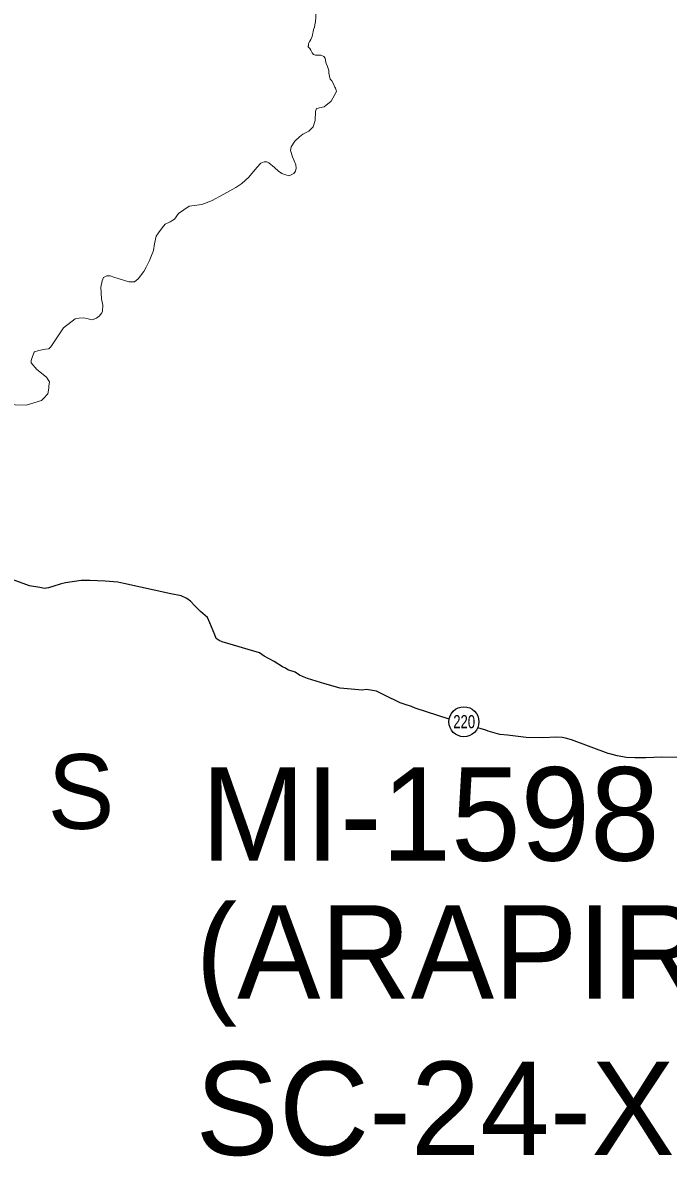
# Model space of a CAD drawing. Extents: x 553962 to 842807, y 8883888 to 9032388.
# Drawn here: x 609594 to 613049, y 8902991 to 8909058 of the extents above; entities that cross this region are included whole.
import ezdxf
from ezdxf.enums import TextEntityAlignment as Align

# ---------------------------------------------------------------- set-up
doc = ezdxf.new("R2010")
doc.units = 0
doc.header["$LTSCALE"] = 200
doc.layers.add('6', color=7, linetype='Continuous', lineweight=13)

msp = doc.modelspace()

# ---------------------------------------------------------------- linework, layer by layer
at = {"layer": '6', "lineweight": 25}
msp.add_line((612071.6, 8905270.5), (612029.8, 8905283.1), dxfattribs=at)
at = {"layer": '6'}
for points in [[(611132.8, 8909169.8), (611140.8, 8909154.6), (611149.8, 8909140.2), (611156.9, 8909130), (611161.9, 8909111.7), (611162.8, 8909101.5), (611162.7, 8909086.2), (611161.5, 8909063.8), (611158.3, 8909046.5), (611155.2, 8909034.3), (611151.1, 8909021.1), (611147.9, 8909008.9), (611144.8, 8908994.6), (611143.7, 8908983.4), (611136.5, 8908968.2), (611130.3, 8908959.1), (611124.1, 8908945.9), (611123, 8908934.7), (611120.9, 8908932.7)], [(611120.8, 8908930.9), (611124, 8908927.7), (611130, 8908919.5), (611136.1, 8908910.3), (611144.1, 8908897), (611151.2, 8908887.8), (611160.3, 8908883.7), (611173.5, 8908884.6), (611188.8, 8908884.5), (611205, 8908876.3), (611213.1, 8908867.1), (611214, 8908854.8), (611219, 8908838.5), (611225, 8908824.2), (611233, 8908802.8), (611232.9, 8908788.5), (611235.8, 8908772.2), (611239.8, 8908754.9), (611248.8, 8908746.7), (611254.9, 8908733.4), (611264.8, 8908712.2), (611264.8, 8908712.1)], [(611264.8, 8908712.2), (611267.8, 8908707.6), (611272.5, 8908697.4), (611273.2, 8908690.4), (611244.6, 8908638.1), (611206.9, 8908607.9), (611166.1, 8908597.7), (611161.7, 8908583.1), (611160.2, 8908534.8), (611148.5, 8908499.8), (611125.2, 8908476.4), (611093.1, 8908461.8), (611075.5, 8908447.2), (611050.7, 8908423.8), (611031.8, 8908393.1), (611027.4, 8908374.1), (611037.6, 8908339), (611055.1, 8908296.7), (611058, 8908279.1), (611053.7, 8908263.1), (611044.9, 8908249.9), (611020.1, 8908238.2), (611002.6, 8908244.1), (610980.7, 8908251.4), (610963.1, 8908263.1), (610941.2, 8908282), (610910.6, 8908306.9), (610900.4, 8908312.7), (610885.8, 8908312.7), (610868.3, 8908305.4), (610847.8, 8908283.5), (610804, 8908230.9), (610767.5, 8908197.3), (610734, 8908175.4), (610671.2, 8908140.3), (610605.5, 8908105.2), (610553, 8908084.8)], [(610553, 8908084.8), (610485.8, 8908076), (610427.4, 8908036.6), (610407, 8908005.9), (610383.6, 8907991.2), (610357.4, 8907979.6), (610341.3, 8907960.6), (610320.9, 8907932.8), (610309.2, 8907915.3), (610299, 8907874.3), (610294.6, 8907839.3), (610272.7, 8907785.2), (610255.2, 8907748.7), (610242, 8907725.3), (610212.8, 8907687.3), (610192.4, 8907671.2), (610163.2, 8907671.2), (610134, 8907680), (610081.5, 8907696.1), (610062.5, 8907703.4), (610045, 8907703.4), (610027.5, 8907694.6), (610020.2, 8907675.6), (610012.9, 8907642), (610015.8, 8907579.2), (610023.1, 8907545.6), (610021.6, 8907513.4), (610017.2, 8907504.6), (610004.1, 8907487.1), (609989.5, 8907476.9), (609966.2, 8907468.1), (609938.4, 8907473.9), (609920.9, 8907478.3), (609894.6, 8907476.9), (609875.6, 8907472.5), (609812.9, 8907424.3), (609763.2, 8907349.7), (609745.7, 8907323.4), (609734.1, 8907311.8), (609716.5, 8907310.3), (609681.5, 8907303), (609658.1, 8907297.1), (609655.2, 8907294.2), (609646.5, 8907270.8), (609640.6, 8907250.4), (609640.6, 8907237.2), (609669.8, 8907202.2), (609722.4, 8907159.8), (609731.1, 8907146.6), (609738.4, 8907134.9), (609734.1, 8907113), (609734.1, 8907101.3), (609728.2, 8907072.1), (609706.3, 8907047.2), (609694.6, 8907035.6), (609612.9, 8907010.7), (609494.7, 8907013.6)]]:
    msp.add_lwpolyline(points, dxfattribs=at)
at = {"layer": '6', "lineweight": 25}
for points in [[(609711.8, 8906029), (609686.4, 8906034.2), (609630.4, 8906044.4), (609398.4, 8906127.4)], [(611876.2, 8905330.5), (611694.3, 8905389.6), (611673.9, 8905398.8), (611640.3, 8905409.1), (611614.9, 8905418.3), (611529.5, 8905459.2), (611487.8, 8905480.7), (611434.8, 8905488.9), (611411.4, 8905485.9), (611293.2, 8905495.3), (611210.8, 8905518.9), (611119.2, 8905548.6), (611091.7, 8905557.8), (611075.4, 8905566), (611053.1, 8905581.3), (611012.4, 8905594.7), (611001.2, 8905603.8), (610983.9, 8905611), (610939.2, 8905638.6), (610887.3, 8905668.2), (610861.9, 8905685.6), (610662.4, 8905744), (610646.2, 8905751.2), (610629.9, 8905762.4), (610621.8, 8905781.8), (610596.6, 8905846), (610582.4, 8905873.6), (610545.9, 8905906.2), (610516.4, 8905936.9), (610492.1, 8905961.4), (610472.8, 8905975.7), (610442.2, 8905990), (610387.3, 8906001.3), (610135.8, 8906056.8), (610104.2, 8906062.9), (610036, 8906069.2), (609954.5, 8906072.4), (609907.6, 8906072.5), (609824.1, 8906060.4), (609794.5, 8906053.3), (609760.8, 8906041.2), (609733.3, 8906033.1), (609711.8, 8906029)], [(612735.8, 8905143.9), (612726.5, 8905147.3), (612530.1, 8905219), (612498.6, 8905228.2), (612481.3, 8905232.3), (612452.7, 8905234.4), (612376.3, 8905230.5), (612288.7, 8905232.7), (612187.9, 8905244.1), (612147.1, 8905248.2), (612085.1, 8905265.6), (612071.6, 8905270.5)], [(613111.5, 8905124.2), (613014.8, 8905127.4), (612929.2, 8905123.5), (612870.1, 8905123.6), (612825.2, 8905124.7), (612775.3, 8905133.9), (612735.8, 8905143.9)]]:
    msp.add_lwpolyline(points, dxfattribs=at)
msp.add_circle((611955.2, 8905316.5), 80.3, dxfattribs=at)

# ---------------------------------------------------------------- texts
at = {"layer": '6', "width": 0.75}
msp.add_text('220', height=70, dxfattribs=at).set_placement((611956.5, 8905281.8), align=Align.CENTER)
at = {"layer": '6'}
for s, height, p in [('A  L  A  G  O  A  S', 400, (605744.9, 8904743.1)), ('MI-1598', 500, (610549.2, 8904573.2)), ('(ARAPIRACA)', 500, (610519.3, 8903834.6)), ('SC-24-X-D-V', 500, (610519.3, 8902997.6))]:
    msp.add_text(s, height=height, dxfattribs=at).set_placement(p)

doc.saveas('drawing.dxf')
